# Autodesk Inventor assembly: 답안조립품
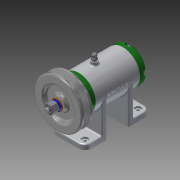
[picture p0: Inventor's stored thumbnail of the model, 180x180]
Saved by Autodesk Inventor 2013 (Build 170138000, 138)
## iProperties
Created: 2017-02
Part Number: 답안조립품
Document SubType Name: Assembly
Designer: Administrator
Author: Administrator
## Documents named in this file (16)
- C:\Users\Administrator\Desktop\470208V1022\답안조립품.iam
- C:\Users\Administrator\Desktop\470208V1022\본체.ipt
- C:\Users\Administrator\Desktop\470208V1022\축.ipt
- C:\Users\Administrator\Desktop\470208V1022\베어링 15 x 32 x 9.ipt
- C:\Users\Administrator\Desktop\470208V1022\뒤커버.ipt
- C:\Users\Administrator\Desktop\470208V1022\앞커버.ipt
- C:\Users\Administrator\Desktop\470208V1022\오일 실 15 25 7.ipt
- C:\Users\Administrator\Desktop\470208V1022\볼트 M4 x 12.ipt
- C:\Users\Administrator\Desktop\470208V1022\니플 M 6 x 0.75.ipt
- C:\Users\Administrator\Desktop\470208V1022\키 3 x 3 x 12.ipt
- C:\Users\Administrator\Desktop\470208V1022\V벨트풀리.ipt
- C:\Users\Administrator\Desktop\470208V1022\와셔 8x17.ipt
- C:\Users\Administrator\Desktop\470208V1022\스프링와셔 8.ipt
- C:\Users\Administrator\Desktop\470208V1022\너트 M 8.ipt
- C:\Users\Administrator\Desktop\470208V1022\와셔 6x11.5.ipt
- C:\Users\Administrator\Desktop\470208V1022\볼트 M 6 x 8.ipt
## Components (11 placed, 3 different names)
1. KS B 2023 6002 - 15 x 32 x 9:2
2. KS B 2023 6002 - 15 x 32 x 9:3
3. V벨트풀리:1
4. ISO 4762 M4 x 12:2
5. ISO 4762 M4 x 12:3
6. ISO 4762 M4 x 12:4
7. ISO 4762 M4 x 12:5
8. ISO 4762 M4 x 12:6
9. ISO 4762 M4 x 12:7
10. ISO 4762 M4 x 12:8
11. ISO 4762 M4 x 12:9
